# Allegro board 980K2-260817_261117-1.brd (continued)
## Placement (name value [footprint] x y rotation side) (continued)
NOREF#2378  -  []  247.95 286.12 90 top
NOREF#2379  -  []  168.42 208.62 0 top
NOREF#2380  -  []  164.64 241.15 90 top
NOREF#2381  -  []  216.26 203.76 90 top
NOREF#2382  -  []  286.32 202.32 0 top
NOREF#2383  -  []  275.58 262.67 90 top
NOREF#2384  -  []  209.55 237.49 0 top
NOREF#2385  -  []  241.75 206.13 0 top
NOREF#2386  -  []  158.64 173.37 90 top
NOREF#2387  -  []  163.97 208.95 0 top
NOREF#2388  -  []  141.83 265.99 0 top
NOREF#2389  -  []  195.05 283.39 0 top
NOREF#2390  -  []  269.12 256.43 90 top
NOREF#2391  -  []  233.6 222.39 0 top
NOREF#2392  -  []  122.2 178.35 0 top
NOREF#2393  -  []  219.55 180.49 90 top
NOREF#2394  -  []  231.19 223.92 0 top
NOREF#2395  -  []  163.97 210.55 90 top
NOREF#2396  -  []  271.24 193.03 90 top
NOREF#2397  -  []  163.84 210.87 90 top
NOREF#2398  -  []  151.11 253.35 0 top
NOREF#2399  -  []  147.77 251.31 0 top
NOREF#2400  -  []  140.83 268.59 90 top
NOREF#2401  -  []  213.64 299.09 0 top
NOREF#2402  -  []  171.22 234.89 90 top
NOREF#2403  -  []  149.84 284.11 0 top
NOREF#2404  -  []  239.27 264.78 90 top
NOREF#2405  -  []  220.43 224.38 90 top
NOREF#2406  -  []  241.75 209.17 0 top
NOREF#2407  -  []  151.76 227.33 0 top
NOREF#2408  -  []  290.89 206.13 0 top
NOREF#2409  -  []  272.63 172.86 0 top
NOREF#2410  -  []  228.35 217.95 90 top
NOREF#2411  -  []  202.57 291.95 0 top
NOREF#2412  -  []  147.43 284.11 90 top
NOREF#2413  -  []  288.42 260.97 90 top
NOREF#2414  -  []  230.48 175.77 0 top
NOREF#2415  -  []  270.15 266.89 90 top
NOREF#2416  -  []  228.99 251.93 0 top
NOREF#2417  -  []  283.97 202.09 0 top
NOREF#2418  -  []  271.24 197.85 90 top
NOREF#2419  -  []  184.16 185.63 90 top
NOREF#2420  -  []  159.4 272 0 top
NOREF#2421  -  []  174.07 210.89 90 top
NOREF#2422  -  []  266.28 257.85 90 top
NOREF#2423  -  []  170.89 269.17 0 top
NOREF#2424  -  []  283.84 210.87 90 top
NOREF#2425  -  []  244.64 241.15 90 top
NOREF#2426  -  []  152.25 272.17 0 top
NOREF#2427  -  []  179.73 238.35 0 top
NOREF#2428  -  []  267.43 278.27 0 top
NOREF#2429  -  []  156.02 251.31 0 top
NOREF#2430  -  []  171.22 294.24 90 top
NOREF#2431  -  []  156.57 182.05 0 top
NOREF#2432  -  []  261.85 246.47 0 top
NOREF#2433  -  []  221.55 205.11 90 top
NOREF#2434  -  []  233.83 172.21 90 top
NOREF#2435  -  []  253.36 201.22 0 top
NOREF#2436  -  []  269.84 213.7 0 top
NOREF#2437  -  []  150.88 228.6 90 top
NOREF#2438  -  []  249.52 270.32 90 top
NOREF#2439  -  []  274.07 196.43 90 top
NOREF#2440  -  []  163.84 267.82 90 top
NOREF#2441  -  []  192.25 272.17 0 top
NOREF#2442  -  []  276.7 193.03 90 top
NOREF#2443  -  []  155.92 195.7 90 top
NOREF#2444  -  []  197.25 180.62 0 top
NOREF#2445  -  []  227.77 252.78 0 top
NOREF#2446  -  []  256.83 287.03 0 top
NOREF#2447  -  []  228.78 282.65 0 top
NOREF#2448  -  []  268.89 392.33 90 top
NOREF#2449  -  []  176.55 254.49 90 top
NOREF#2450  -  []  195.49 228.7 90 top
NOREF#2451  -  []  197.37 240.3 90 top
NOREF#2452  -  []  237.04 244.35 0 top
NOREF#2453  -  []  173.34 17.15 90 top
NOREF#2454  -  []  153.95 256.75 0 top
NOREF#2455  -  []  150.77 219.22 90 top
NOREF#2456  -  []  169.52 272.86 90 top
NOREF#2457  -  []  191.76 167.33 0 top
NOREF#2458  -  []  164.44 232.28 90 top
NOREF#2459  -  []  151.76 167.33 0 top
NOREF#2460  -  []  245.38 226.23 0 top
NOREF#2461  -  []  203.84 270.87 90 top
NOREF#2462  -  []  173.36 261.22 0 top
NOREF#2463  -  []  188.32 182.05 0 top
NOREF#2464  -  []  236.84 227.33 0 top
NOREF#2465  -  []  142.81 186.81 0 top
NOREF#2466  -  []  218.95 264.09 0 top
NOREF#2467  -  []  226.16 253.35 0 top
NOREF#2468  -  []  288.42 265.58 0 top
NOREF#2469  -  []  139.08 265.79 0 top
NOREF#2470  -  []  237.04 244.35 0 top
NOREF#2471  -  []  253.62 229.09 90 top
NOREF#2472  -  []  279.27 200.97 90 top
NOREF#2473  -  []  254.09 267.27 90 top
NOREF#2474  -  []  232.25 218.02 0 top
NOREF#2475  -  []  215.65 244.35 0 top
NOREF#2476  -  []  125.38 226.23 0 top
NOREF#2477  -  []  141.55 205.11 90 top
NOREF#2478  -  []  203.97 260.64 90 top
NOREF#2479  -  []  152.61 456.29 0 top
NOREF#2480  -  []  147.3 280.35 0 top
NOREF#2481  -  []  277.37 256.43 90 top
NOREF#2482  -  []  156.7 197.85 90 top
NOREF#2483  -  []  129.17 291.95 0 top
NOREF#2484  -  []  135.11 201.22 90 top
NOREF#2485  -  []  276.79 231.3 0 top
NOREF#2486  -  []  144.16 196.43 90 top
NOREF#2487  -  []  155.56 235.77 0 top
NOREF#2488  -  []  229.12 240.3 90 top
NOREF#2489  -  []  275.15 176.17 90 top
NOREF#2490  -  []  270.6 233.69 90 top
NOREF#2491  -  []  159.4 205.9 0 top
NOREF#2492  -  []  224.04 185.96 0 top
NOREF#2493  -  []  214.43 292.23 0 top
NOREF#2494  -  []  156.33 227.9 90 top
NOREF#2495  -  []  264.24 18.69 0 top
NOREF#2496  -  []  273.39 253.03 90 top
NOREF#2497  -  []  270.48 235.77 0 top
NOREF#2498  -  []  163.4 236.38 0 top
NOREF#2499  -  []  191.91 251.6 90 top
NOREF#2500  -  []  195.56 175.77 0 top
NOREF#2501  -  []  226.16 226.14 90 top
NOREF#2502  -  []  283.97 267.5 90 top
NOREF#2503  -  []  249.52 210.32 90 top
NOREF#2504  -  []  168.54 262.09 0 top
NOREF#2505  -  []  234.07 256.43 90 top
NOREF#2506  -  []  264.04 256.75 0 top
NOREF#2507  -  []  289.52 210.32 90 top
NOREF#2508  -  []  230.88 168.6 90 top
NOREF#2509  -  []  147.45 269.24 0 top
NOREF#2510  -  []  240.23 236.17 90 top
NOREF#2511  -  []  269.12 240.3 90 top
NOREF#2512  -  []  168.54 202.09 0 top
NOREF#2513  -  []  277.03 238.07 0 top
NOREF#2514  -  []  268.32 198.18 0 top
NOREF#2515  -  []  218.97 211.91 90 top
NOREF#2516  -  []  241.44 184.35 0 top
NOREF#2517  -  []  209.55 237.49 0 top
NOREF#2518  -  []  271.79 256.75 0 top
NOREF#2519  -  []  178.97 211.91 90 top
NOREF#2520  -  []  270.88 168.6 90 top
NOREF#2521  -  []  138.75 457.2 0 top
NOREF#2522  -  []  239.4 202.09 0 top
NOREF#2523  -  []  84.45 359.42 0 top
NOREF#2524  -  []  175.02 208.14 90 top
NOREF#2525  -  []  157.71 172.86 0 top
NOREF#2526  -  []  182.03 229.03 90 top
NOREF#2527  -  []  274.33 207.37 90 top
NOREF#2528  -  []  178.95 201.55 0 top
NOREF#2529  -  []  273.56 173.37 90 top
NOREF#2530  -  []  157.37 256.43 90 top
NOREF#2531  -  []  150.63 259.3 0 top
NOREF#2532  -  []  277.25 251.93 0 top
NOREF#2533  -  []  273.18 211.85 90 top
NOREF#2534  -  []  239.4 264.45 90 top
NOREF#2535  -  []  224.04 196.75 0 top
NOREF#2536  -  []  258.95 206.12 0 top
NOREF#2537  -  []  239.27 271.67 0 top
NOREF#2538  -  []  272.25 282.59 0 top
NOREF#2539  -  []  190.6 173.69 0 top
NOREF#2540  -  []  221.55 209.94 90 top
NOREF#2541  -  []  152.72 192.78 0 top
NOREF#2542  -  []  284.95 260.42 90 top
NOREF#2543  -  []  225.41 226.99 90 top
NOREF#2544  -  []  192.13 274.25 0 top
NOREF#2545  -  []  186.43 296.46 90 top
NOREF#2546  -  []  222.87 286.99 0 top
NOREF#2547  -  []  239.72 274.65 90 top
NOREF#2548  -  []  197.71 173.69 90 top
NOREF#2549  -  []  255.11 261.22 90 top
NOREF#2550  -  []  230.77 283.79 90 top
NOREF#2551  -  []  190.77 279.22 90 top
NOREF#2552  -  []  153.83 172.21 90 top
NOREF#2553  -  []  203.04 236.5 90 top
NOREF#2554  -  []  283.97 205.9 0 top
NOREF#2555  -  []  191.73 172.54 0 top
NOREF#2556  -  []  243.84 211.67 0 top
NOREF#2557  -  []  211.25 184.35 0 top
NOREF#2558  -  []  228.19 187.71 0 top
NOREF#2559  -  []  197.18 236.17 90 top
NOREF#2560  -  []  236.7 181.72 90 top
NOREF#2561  -  []  196.52 221.12 0 top
NOREF#2562  -  []  163.97 267.5 90 top
NOREF#2563  -  []  100.95 17.15 0 top
NOREF#2564  -  []  195.05 274.25 0 top
NOREF#2565  -  []  192.13 284.66 0 top
NOREF#2566  -  []  173.45 184.35 0 top
NOREF#2567  -  []  148.99 191.93 0 top
NOREF#2568  -  []  272.25 212.18 90 top
NOREF#2569  -  []  279.4 267.5 90 top
NOREF#2570  -  []  159.4 265.9 0 top
NOREF#2571  -  []  188.44 181.72 90 top
NOREF#2572  -  []  221.55 269.94 90 top
NOREF#2573  -  []  170.89 206.13 0 top
NOREF#2574  -  []  173.65 179.15 0 top
NOREF#2575  -  []  248.94 221.73 0 top
NOREF#2576  -  []  146.28 197.85 90 top
NOREF#2577  -  []  259.55 234.49 0 top
NOREF#2578  -  []  161.84 235.2 0 top
NOREF#2579  -  []  273.6 276.55 0 top
NOREF#2580  -  []  178.95 208.91 0 top
NOREF#2581  -  []  273.98 178.07 0 top
NOREF#2582  -  []  167.95 286.12 90 top
NOREF#2583  -  []  171.65 293.3 90 top
NOREF#2584  -  []  270.97 239.57 90 top
NOREF#2585  -  []  276.57 182.05 0 top
NOREF#2586  -  []  227.99 238.35 0 top
NOREF#2587  -  []  185.42 274.72 90 top
NOREF#2588  -  []  194.33 204.33 90 top
NOREF#2589  -  []  237.74 166.36 90 top
NOREF#2590  -  []  267.99 238.35 0 top
NOREF#2591  -  []  259.08 205.79 0 top
NOREF#2592  -  []  129.44 260.67 0 top
NOREF#2593  -  []  243.84 210.87 90 top
NOREF#2594  -  []  254.07 210.89 90 top
NOREF#2595  -  []  161.12 188.11 90 top
NOREF#2596  -  []  294.09 200.42 90 top
NOREF#2597  -  []  228.78 228.49 0 top
NOREF#2598  -  []  214.43 292.23 0 top
NOREF#2599  -  []  154.39 222.02 90 top
NOREF#2600  -  []  233.56 233.37 90 top
NOREF#2601  -  []  159.4 267.5 90 top
NOREF#2602  -  []  191.19 223.92 0 top
NOREF#2603  -  []  279.22 195.7 90 top
NOREF#2604  -  []  163.84 270.87 90 top
NOREF#2605  -  []  277.71 172.86 0 top
NOREF#2606  -  []  179.08 268.59 0 top
NOREF#2607  -  []  204.95 260.42 90 top
NOREF#2608  -  []  159.27 274.21 0 top
NOREF#2609  -  []  137.28 286.47 0 top
NOREF#2610  -  []  261.03 207.69 90 top
NOREF#2611  -  []  179.55 294.49 0 top
NOREF#2612  -  []  226.28 193.03 90 top
NOREF#2613  -  []  232.63 233.69 0 top
NOREF#2614  -  []  232.51 235.77 0 top
NOREF#2615  -  []  156.8 214.65 90 top
NOREF#2616  -  []  151.7 274.65 90 top
NOREF#2617  -  []  196.61 173.37 90 top
NOREF#2618  -  []  178.97 18.69 0 top
NOREF#2619  -  []  174.34 82.65 0 top
NOREF#2620  -  []  211.05 232.28 90 top
NOREF#2621  -  []  195.17 221.32 90 top
NOREF#2622  -  []  147.3 226.19 0 top
NOREF#2623  -  []  237.37 256.43 90 top
NOREF#2624  -  []  209.17 291.95 0 top
NOREF#2625  -  []  85.84 157.62 0 top
NOREF#2626  -  []  154.39 216.17 90 top
NOREF#2627  -  []  150.15 206.89 90 top
NOREF#2628  -  []  159.44 179.15 0 top
NOREF#2629  -  []  288.42 261.77 0 top
NOREF#2630  -  []  288.39 396.29 0 top
NOREF#2631  -  []  234.07 196.43 90 top
NOREF#2632  -  []  183.49 187.06 90 top
NOREF#2633  -  []  131.22 294.89 90 top
NOREF#2634  -  []  153.18 211.85 90 top
NOREF#2635  -  []  193.39 253.03 90 top
NOREF#2636  -  []  150.6 233.69 90 top
NOREF#2637  -  []  85.59 155.57 90 top
NOREF#2638  -  []  94.87 102.74 90 top
NOREF#2639  -  []  251.25 244.35 0 top
NOREF#2640  -  []  268.44 257.85 90 top
NOREF#2641  -  []  156.57 245.63 90 top
NOREF#2642  -  []  283.97 264.45 90 top
NOREF#2643  -  []  155.17 212.18 0 top
NOREF#2644  -  []  274.39 222.02 90 top
NOREF#2645  -  []  149.72 226.19 0 top
NOREF#2646  -  []  239.27 213.41 90 top
NOREF#2647  -  []  231.95 238.07 0 top
NOREF#2648  -  []  131.26 244.35 0 top
NOREF#2649  -  []  259.08 201.22 0 top
NOREF#2650  -  []  217.29 247.78 0 top
NOREF#2651  -  []  252.87 227.4 90 top
NOREF#2652  -  []  271.19 283.92 0 top
NOREF#2653  -  []  203.97 207.5 90 top
NOREF#2654  -  []  288.54 202.09 0 top
NOREF#2655  -  []  146.96 256.43 90 top
NOREF#2656  -  []  239.44 179.15 0 top
NOREF#2657  -  []  228.78 288.49 0 top
NOREF#2658  -  []  268.32 258.18 0 top
NOREF#2659  -  []  159.4 262.09 0 top
NOREF#2660  -  []  246.32 262.32 0 top
NOREF#2661  -  []  263.49 187.06 90 top
NOREF#2662  -  []  153.18 217.69 90 top
NOREF#2663  -  []  273.94 191.93 0 top
NOREF#2664  -  []  258.35 204.47 0 top
NOREF#2665  -  []  147.77 197.6 0 top
NOREF#2666  -  []  279.4 268.95 0 top
NOREF#2667  -  []  196.57 258.18 0 top
NOREF#2668  -  []  261.55 262.57 90 top
NOREF#2669  -  []  250.89 206.13 0 top
NOREF#2670  -  []  268.44 241.72 90 top
NOREF#2671  -  []  239.4 270.55 90 top
NOREF#2672  -  []  198.47 82.65 0 top
NOREF#2673  -  []  272.87 248.11 90 top
NOREF#2674  -  []  231.91 256.43 90 top
NOREF#2675  -  []  228.32 258.18 0 top
NOREF#2676  -  []  154.33 207.37 90 top
NOREF#2677  -  []  155.15 176.17 90 top
NOREF#2678  -  []  152.51 175.77 0 top
NOREF#2679  -  []  183.36 187.38 0 top
NOREF#2680  -  []  153.95 251.93 0 top
NOREF#2681  -  []  219.55 234.49 0 top
NOREF#2682  -  []  249.52 204.23 90 top
NOREF#2683  -  []  189.67 250.01 0 top
NOREF#2684  -  []  80.49 135.25 0 top
NOREF#2685  -  []  283.84 261.77 0 top
NOREF#2686  -  []  227.77 192.78 0 top
NOREF#2687  -  []  267.3 280.35 0 top
NOREF#2688  -  []  156.57 253.35 0 top
NOREF#2689  -  []  192.72 197.6 0 top
NOREF#2690  -  []  199.4 204.45 90 top
NOREF#2691  -  []  275.17 216.75 0 top
NOREF#2692  -  []  189.24 185.31 90 top
NOREF#2693  -  []  223.49 187.06 90 top
NOREF#2694  -  []  234.39 222.02 90 top
NOREF#2695  -  []  254.43 292.23 0 top
NOREF#2696  -  []  272.25 222.59 0 top
NOREF#2697  -  []  260.59 244.98 90 top
NOREF#2698  -  []  269.72 226.19 0 top
NOREF#2699  -  []  279.72 283.79 90 top
NOREF#2700  -  []  152.25 222.59 90 top
NOREF#2701  -  []  156.7 257.85 90 top
NOREF#2702  -  []  281.75 274.76 0 top
NOREF#2703  -  []  148.81 190.88 90 top
NOREF#2704  -  []  273.6 216.55 0 top
NOREF#2705  -  []  255.02 268.14 90 top
NOREF#2706  -  []  302.59 389.27 90 top
NOREF#2707  -  []  284.95 204.23 90 top
NOREF#2708  -  []  192.63 233.69 90 top
NOREF#2709  -  []  260.83 261.22 90 top
NOREF#2710  -  []  190.15 206.89 90 top
NOREF#2711  -  []  193.83 232.21 90 top
NOREF#2712  -  []  232.25 282.59 90 top
NOREF#2713  -  []  283.84 207.82 90 top
NOREF#2714  -  []  264.04 185.96 0 top
NOREF#2715  -  []  236.52 221.12 0 top
NOREF#2716  -  []  131.05 292.28 90 top
NOREF#2717  -  []  128.94 265.53 0 top
NOREF#2718  -  []  234.39 226.59 90 top
NOREF#2719  -  []  234.33 264.33 90 top
NOREF#2720  -  []  227.3 226.19 0 top
NOREF#2721  -  []  238.91 172.21 90 top
NOREF#2722  -  []  256.98 205.11 90 top
NOREF#2723  -  []  259.08 263.76 0 top
NOREF#2724  -  []  270.77 273.37 90 top
NOREF#2725  -  []  260.43 284.38 90 top
NOREF#2726  -  []  279.27 201.77 0 top
NOREF#2727  -  []  194.33 264.33 90 top
NOREF#2728  -  []  283.97 270.55 90 top
NOREF#2729  -  []  279.4 207.5 90 top
NOREF#2730  -  []  284.95 212.86 90 top
NOREF#2731  -  []  176.74 456.29 0 top
NOREF#2732  -  []  221.6 17.15 0 top
NOREF#2733  -  []  275.49 18.69 90 top
NOREF#2734  -  []  136.98 205.11 90 top
NOREF#2735  -  []  148.78 184.35 0 top
NOREF#2736  -  []  267.3 220.35 0 top
NOREF#2737  -  []  273.27 193.35 0 top
NOREF#2738  -  []  187.8 264.99 90 top
NOREF#2739  -  []  239.4 265.9 0 top
NOREF#2740  -  []  201.84 235.2 0 top
NOREF#2741  -  []  242.2 178.35 0 top
NOREF#2742  -  []  156.02 181.47 0 top
NOREF#2743  -  []  196.1 216.42 90 top
NOREF#2744  -  []  284.95 210.32 90 top
NOREF#2745  -  []  172.37 392.33 90 top
NOREF#2746  -  []  146.17 226.14 90 top
NOREF#2747  -  []  259.72 213.6 90 top
NOREF#2748  -  []  191.79 196.75 0 top
NOREF#2749  -  []  228.32 185.63 0 top
NOREF#2750  -  []  159.27 205.58 0 top
NOREF#2751  -  []  233.76 195.7 90 top
NOREF#2752  -  []  230.2 389.27 90 top
NOREF#2753  -  []  197.25 256.75 0 top
NOREF#2754  -  []  260.95 261.55 90 top
NOREF#2755  -  []  244.64 181.15 90 top
NOREF#2756  -  []  153.27 253.35 0 top
NOREF#2757  -  []  175.02 268.14 90 top
NOREF#2758  -  []  193.95 191.93 0 top
NOREF#2759  -  []  165.38 286.23 0 top
NOREF#2760  -  []  149.12 191.6 90 top
NOREF#2761  -  []  272.25 278.02 0 top
NOREF#2762  -  []  239.65 212.56 0 top
NOREF#2763  -  []  278.64 173.37 90 top
NOREF#2764  -  []  191.19 288.49 0 top
NOREF#2765  -  []  284.95 207.27 90 top
NOREF#2766  -  []  168.54 260.64 90 top
NOREF#2767  -  []  146.16 200.17 90 top
NOREF#2768  -  []  153.56 173.37 90 top
NOREF#2769  -  []  259.73 178.35 0 top
NOREF#2770  -  []  231.76 227.33 0 top
NOREF#2771  -  []  199.72 279.22 90 top
NOREF#2772  -  []  266.28 197.85 90 top
NOREF#2773  -  []  164.95 212.86 90 top
NOREF#2774  -  []  199.44 179.15 0 top
NOREF#2775  -  []  191.11 193.35 0 top
NOREF#2776  -  []  139.55 294.49 0 top
NOREF#2777  -  []  187.8 269.99 0 top
NOREF#2778  -  []  216.98 205.11 90 top
NOREF#2779  -  []  271.76 167.33 0 top
NOREF#2780  -  []  236.52 285.69 0 top
NOREF#2781  -  []  157.81 389.27 90 top
NOREF#2782  -  []  131.84 21.69 90 top
NOREF#2783  -  []  195.68 173.69 0 top
NOREF#2784  -  []  159.27 208.62 0 top
NOREF#2785  -  []  151.71 171.3 0 top
NOREF#2786  -  []  229.84 219.54 90 top
NOREF#2787  -  []  272.25 218.02 0 top
NOREF#2788  -  []  268.32 185.63 0 top
NOREF#2789  -  []  175.84 262.57 90 top
NOREF#2790  -  []  238.64 233.37 90 top
NOREF#2791  -  []  151.11 193.35 0 top
NOREF#2792  -  []  270.97 179.57 90 top
NOREF#2793  -  []  165.04 293.3 90 top
NOREF#2794  -  []  199.06 238.07 0 top
NOREF#2795  -  []  269.67 250.01 0 top
NOREF#2796  -  []  189.12 240.3 90 top
NOREF#2797  -  []  279.27 264.78 90 top
NOREF#2798  -  []  227.45 269.24 0 top
NOREF#2799  -  []  148.78 244.35 0 top
NOREF#2800  -  []  242.57 291.95 0 top
NOREF#2801  -  []  232.87 188.11 90 top
NOREF#2802  -  []  234.78 176.5 90 top
NOREF#2803  -  []  196.79 171.3 0 top
NOREF#2804  -  []  180.95 201.55 90 top
NOREF#2805  -  []  161.44 184.35 0 top
NOREF#2806  -  []  216.98 265.11 90 top
NOREF#2807  -  []  130.92 291.95 90 top
NOREF#2808  -  []  277.37 196.43 90 top
NOREF#2809  -  []  162.2 178.35 0 top
NOREF#2810  -  []  271.19 278.07 0 top
NOREF#2811  -  []  222.87 273.02 0 top
NOREF#2812  -  []  153.95 191.93 0 top
NOREF#2813  -  []  218.95 208.91 0 top
NOREF#2814  -  []  209.55 237.49 0 top
NOREF#2815  -  []  194.78 236.5 90 top
NOREF#2816  -  []  263.36 253.35 0 top
NOREF#2817  -  []  279.22 190.88 90 top
NOREF#2818  -  []  259.4 458.49 0 top
NOREF#2819  -  []  152.63 173.69 0 top
NOREF#2820  -  []  147.3 220.35 0 top
NOREF#2821  -  []  189.84 284.11 90 top
NOREF#2822  -  []  236.7 193.03 90 top
NOREF#2823  -  []  275.17 212.18 0 top
NOREF#2824  -  []  168.42 205.58 0 top
NOREF#2825  -  []  122.85 237.22 0 top
NOREF#2826  -  []  147.99 178.35 0 top
NOREF#2827  -  []  230.97 239.57 90 top
NOREF#2828  -  []  148.32 193.35 0 top
NOREF#2829  -  []  279.4 273.09 90 top
NOREF#2830  -  []  250.02 214.45 0 top
NOREF#2831  -  []  190.98 244.35 0 top
NOREF#2832  -  []  197.25 240.62 0 top
NOREF#2833  -  []  159.4 214.54 0 top
NOREF#2834  -  []  181.85 246.47 0 top
NOREF#2835  -  []  261.85 306.46 0 top
NOREF#2836  -  []  194.33 267.37 90 top
NOREF#2837  -  []  235.17 216.75 90 top
NOREF#2838  -  []  180.83 201.22 90 top
NOREF#2839  -  []  288.42 208.62 0 top
NOREF#2840  -  []  106.68 128.02 0 top
NOREF#2841  -  []  261.55 265.11 90 top
NOREF#2842  -  []  140.95 261.55 90 top
NOREF#2843  -  []  186.96 191.6 90 top
NOREF#2844  -  []  134.04 210.63 90 top
NOREF#2845  -  []  155.68 233.69 0 top
NOREF#2846  -  []  243.97 207.5 90 top
NOREF#2847  -  []  146.16 253.35 0 top
NOREF#2848  -  []  149.84 224.11 90 top
NOREF#2849  -  []  273.18 244.35 0 top
NOREF#2850  -  []  228.35 283.79 90 top
NOREF#2851  -  []  155.17 216.75 90 top
NOREF#2852  -  []  138.95 206.12 0 top
NOREF#2853  -  []  197.18 176.17 90 top
NOREF#2854  -  []  274.39 216.17 90 top
NOREF#2855  -  []  244.95 210.32 90 top
NOREF#2856  -  []  187.77 252.78 0 top
NOREF#2857  -  []  144.04 256.75 0 top
NOREF#2858  -  []  273.6 282.39 0 top
NOREF#2859  -  []  188.81 255.7 90 top
NOREF#2860  -  []  229.84 284.11 90 top
NOREF#2861  -  []  239.27 200.97 90 top
NOREF#2862  -  []  135.24 261.55 90 top
NOREF#2863  -  []  152.72 252.5 0 top
NOREF#2864  -  []  190.97 255.7 90 top
NOREF#2865  -  []  197.04 184.35 0 top
NOREF#2866  -  []  155.05 223.39 0 top
NOREF#2867  -  []  170.89 262.32 0 top
NOREF#2868  -  []  202.2 178.35 0 top
NOREF#2869  -  []  273.39 193.03 90 top
NOREF#2870  -  []  235.68 173.69 0 top
NOREF#2871  -  []  232.63 173.69 0 top
NOREF#2872  -  []  150.6 233.69 0 top
NOREF#2873  -  []  283.97 204.45 90 top
NOREF#2874  -  []  203.97 202.09 0 top
NOREF#2875  -  []  191.71 171.3 0 top
NOREF#2876  -  []  169.52 210.32 90 top
NOREF#2877  -  []  224.16 245.63 90 top
NOREF#2878  -  []  159.65 212.56 0 top
NOREF#2879  -  []  243.4 236.38 0 top
NOREF#2880  -  []  229.24 245.31 90 top
NOREF#2881  -  []  248.54 200.64 90 top
NOREF#2882  -  []  227.23 18.69 90 top
NOREF#2883  -  []  149.24 245.31 90 top
NOREF#2884  -  []  155.49 228.7 90 top
NOREF#2885  -  []  157.37 240.3 90 top
NOREF#2886  -  []  163.84 213.41 90 top
NOREF#2887  -  []  251.21 294.89 90 top
NOREF#2888  -  []  137.28 272.5 0 top
NOREF#2889  -  []  228.44 193.03 90 top
NOREF#2890  -  []  230.41 168.7 90 top
NOREF#2891  -  []  254.09 207.27 90 top
NOREF#2892  -  []  193.6 222.39 0 top
NOREF#2893  -  []  254.09 264.23 90 top
NOREF#2894  -  []  276.8 280.49 90 top
NOREF#2895  -  []  239.27 204.78 90 top
NOREF#2896  -  []  150.77 279.22 90 top
NOREF#2897  -  []  275.51 454.29 90 top
NOREF#2898  -  []  270.77 279.22 90 top
NOREF#2899  -  []  181.6 248.12 0 top
NOREF#2900  -  []  179.55 240.49 90 top
NOREF#2901  -  []  129.17 231.95 0 top
NOREF#2902  -  []  124.32 291.95 90 top
NOREF#2903  -  []  199.4 274.54 0 top
NOREF#2904  -  []  275.68 173.69 90 top
NOREF#2905  -  []  197.37 251.6 90 top
NOREF#2906  -  []  254.04 210.63 90 top
NOREF#2907  -  []  270.97 195.7 90 top
NOREF#2908  -  []  130.58 263.21 90 top
NOREF#2909  -  []  190.77 213.37 90 top
NOREF#2910  -  []  232.13 214.25 0 top
NOREF#2911  -  []  147.43 218.27 90 top
NOREF#2912  -  []  269.84 284.11 0 top
NOREF#2913  -  []  243.97 202.09 0 top
NOREF#2914  -  []  195.17 272.17 90 top
NOREF#2915  -  []  135.15 265.24 90 top
NOREF#2916  -  []  266.01 195.7 90 top
NOREF#2917  -  []  210.89 202.32 0 top
NOREF#2918  -  []  146.96 191.6 90 top
NOREF#2919  -  []  268.99 240.62 0 top
NOREF#2920  -  []  188.81 250.88 90 top
NOREF#2921  -  []  243.92 289.94 0 top
NOREF#2922  -  []  199.22 179.57 90 top
NOREF#2923  -  []  86.61 153.16 0 top
NOREF#2924  -  []  244.95 204.23 90 top
NOREF#2925  -  []  186.28 197.85 90 top
NOREF#2926  -  []  231.24 193.03 90 top
NOREF#2927  -  []  140.43 224.38 90 top
NOREF#2928  -  []  259.73 238.35 0 top
NOREF#2929  -  []  239.4 214.54 0 top
NOREF#2930  -  []  248.42 265.58 0 top
NOREF#2931  -  []  141.6 248.12 0 top
NOREF#2932  -  []  283.84 273.41 90 top
NOREF#2933  -  []  188.78 222.65 0 top
NOREF#2934  -  []  191.98 280.75 90 top
NOREF#2935  -  []  216.55 220.49 0 top
NOREF#2936  -  []  199.22 255.7 90 top
NOREF#2937  -  []  215.02 268.14 90 top
NOREF#2938  -  []  143.49 193.03 90 top
NOREF#2939  -  []  243.84 273.41 90 top
NOREF#2940  -  []  159.24 244.35 0 top
NOREF#2941  -  []  239.27 211.67 0 top
NOREF#2942  -  []  168.54 204.45 90 top
NOREF#2943  -  []  188.35 283.79 90 top
NOREF#2944  -  []  252.55 284.49 0 top
NOREF#2945  -  []  283.97 274.54 0 top
NOREF#2946  -  []  266.96 251.6 90 top
NOREF#2947  -  []  157.04 184.35 0 top
NOREF#2948  -  []  268.99 191.93 0 top
NOREF#2949  -  []  321.5 18.69 0 top
NOREF#2950  -  []  156.02 236.37 0 top
NOREF#2951  -  []  280.23 176.17 90 top
NOREF#2952  -  []  207.98 226.38 90 top
NOREF#2953  -  []  184.16 196.43 90 top
NOREF#2954  -  []  184.16 245.63 90 top
NOREF#2955  -  []  228.99 191.93 0 top
NOREF#2956  -  []  152.11 171.4 0 top
NOREF#2957  -  []  191.11 260.17 90 top
NOREF#2958  -  []  275.96 228.6 90 top
NOREF#2959  -  []  236.45 187.71 0 top
NOREF#2960  -  []  259.72 273.6 90 top
NOREF#2961  -  []  161.75 206.13 0 top
NOREF#2962  -  []  156.7 193.03 90 top
NOREF#2963  -  []  277.59 235.77 0 top
NOREF#2964  -  []  196.38 181.15 90 top
NOREF#2965  -  []  266.43 296.46 90 top
NOREF#2966  -  []  146.01 195.7 90 top
NOREF#2967  -  []  235.96 168.6 90 top
NOREF#2968  -  []  284.95 264.23 90 top
NOREF#2969  -  []  170.89 202.32 0 top
NOREF#2970  -  []  199.06 178.07 0 top
NOREF#2971  -  []  269.72 275.77 0 top
NOREF#2972  -  []  232.63 233.69 90 top
NOREF#2973  -  []  165.04 233.3 90 top
NOREF#2974  -  []  155.68 173.69 0 top
NOREF#2975  -  []  179.73 178.35 0 top
NOREF#2976  -  []  279.27 204.78 90 top
NOREF#2977  -  []  243.97 268.95 0 top
NOREF#2978  -  []  256.55 194.49 90 top
NOREF#2979  -  []  232.25 222.59 0 top
NOREF#2980  -  []  199.22 250.88 90 top
NOREF#2981  -  []  283.97 200.64 90 top
NOREF#2982  -  []  168.94 221.73 0 top
NOREF#2983  -  []  231.11 258.18 0 top
NOREF#2984  -  []  203.04 176.5 90 top
NOREF#2985  -  []  247.95 226.12 90 top
NOREF#2986  -  []  169.17 231.95 0 top
NOREF#2987  -  []  199.4 208.95 0 top
NOREF#2988  -  []  254.09 260.42 90 top
NOREF#2989  -  []  155.58 202.67 90 top
NOREF#2990  -  []  259.55 240.49 90 top
NOREF#2991  -  []  121.84 235.2 0 top
NOREF#2992  -  []  218.35 267.01 0 top
NOREF#2993  -  []  230.98 184.35 0 top
NOREF#2994  -  []  254.09 204.23 90 top
NOREF#2995  -  []  187.03 231.4 0 top
NOREF#2996  -  []  209.52 207.27 90 top
NOREF#2997  -  []  276.8 274.65 90 top
NOREF#2998  -  []  258.35 269.04 0 top
NOREF#2999  -  []  188.99 196.75 0 top
NOREF#3000  -  []  192.51 235.77 0 top
NOREF#3001  -  []  232.13 274.25 0 top
NOREF#3002  -  []  248.54 208.95 0 top
NOREF#3003  -  []  168.42 201.77 0 top
NOREF#3004  -  []  258.95 266.12 0 top
NOREF#3005  -  []  263.89 245.24 90 top
NOREF#3006  -  []  196.33 227.9 90 top
NOREF#3007  -  []  276.7 241.72 90 top
NOREF#3008  -  []  133.66 179.15 0 top
NOREF#3009  -  []  158.91 232.21 90 top
NOREF#3010  -  []  99.98 392.33 90 top
NOREF#3011  -  []  132.55 250.49 90 top
NOREF#3012  -  []  122.2 178.35 0 top
NOREF#3013  -  []  131.26 184.35 0 top
NOREF#3014  -  []  149.29 276.17 90 top
NOREF#3015  -  []  139.08 268.59 0 top
NOREF#3016  -  []  268.32 245.63 0 top
NOREF#3017  -  []  233.6 282.39 0 top
NOREF#3018  -  []  176.26 263.76 90 top
NOREF#3019  -  []  157.25 180.62 0 top
NOREF#3020  -  []  179.73 178.35 0 top
NOREF#3021  -  []  163.97 213.09 90 top
NOREF#3022  -  []  188.44 193.03 90 top
NOREF#3023  -  []  158.11 232.1 0 top
NOREF#3024  -  []  275.17 276.75 0 top
NOREF#3025  -  []  288.42 268.62 0 top
NOREF#3026  -  []  138.83 292.23 0 top
NOREF#3027  -  []  163.97 265.9 0 top
NOREF#3028  -  []  258.95 204.09 0 top
NOREF#3029  -  []  192.13 214.25 0 top
NOREF#3030  -  []  124.55 148.49 90 top
NOREF#3031  -  []  168.54 265.9 0 top
NOREF#3032  -  []  191.98 226.59 90 top
NOREF#3033  -  []  235.05 274.25 0 top
NOREF#3034  -  []  272.11 171.4 0 top
NOREF#3035  -  []  223.36 253.35 0 top
NOREF#3036  -  []  176.98 265.11 90 top
NOREF#3037  -  []  88.14 134.87 0 top
NOREF#3038  -  []  209.52 212.86 90 top
NOREF#3039  -  []  272.13 274.25 0 top
NOREF#3040  -  []  90.48 16.49 0 top
NOREF#3041  -  []  248.54 267.5 90 top
NOREF#3042  -  []  247.98 226.38 90 top
NOREF#3043  -  []  246.32 212.22 0 top
NOREF#3044  -  []  141.85 232.5 0 top
NOREF#3045  -  []  265.42 274.72 90 top
NOREF#3046  -  []  238.64 173.37 90 top
NOREF#3047  -  []  167.98 286.38 90 top
NOREF#3048  -  []  135.66 244.35 0 top
NOREF#3049  -  []  185.61 257.6 0 top
NOREF#3050  -  []  270.41 168.7 90 top
NOREF#3051  -  []  191.46 227 0 top
NOREF#3052  -  []  188.32 258.18 0 top
NOREF#3053  -  []  122.44 232.28 0 top
NOREF#3054  -  []  143.61 456.29 90 top
NOREF#3055  -  []  174.09 204.23 90 top
NOREF#3056  -  []  222.03 289.03 90 top
NOREF#3057  -  []  238.11 232.1 0 top
NOREF#3058  -  []  278.91 172.21 90 top
NOREF#3059  -  []  237.71 173.69 0 top
NOREF#3060  -  []  276.57 245.63 90 top
NOREF#3061  -  []  244.95 207.27 90 top
NOREF#3062  -  []  123.4 236.38 0 top
NOREF#3063  -  []  208.54 260.64 90 top
NOREF#3064  -  []  136.63 292.23 0 top
NOREF#3065  -  []  186.01 184.91 90 top
NOREF#3066  -  []  251.05 292.28 90 top
NOREF#3067  -  []  193.03 172.1 0 top
NOREF#3068  -  []  229.72 281.62 0 top
NOREF#3069  -  []  228.95 206.89 0 top
NOREF#3070  -  []  150.6 173.69 90 top
NOREF#3071  -  []  271.11 198.18 0 top
NOREF#3072  -  []  288.54 208.95 0 top
NOREF#3073  -  []  191.71 231.3 0 top
NOREF#3074  -  []  150.98 184.35 0 top
NOREF#3075  -  []  163.4 296.38 0 top
NOREF#3076  -  []  264.04 191.93 0 top
NOREF#3077  -  []  196.02 197.6 0 top
NOREF#3078  -  []  184.04 196.75 0 top
NOREF#3079  -  []  214.09 264.23 90 top
NOREF#3080  -  []  260.95 264.09 90 top
NOREF#3081  -  []  243.84 271.67 0 top
NOREF#3082  -  []  122.57 291.95 0 top
NOREF#3083  -  []  239.22 179.57 90 top
NOREF#3084  -  []  206.32 269.17 0 top
NOREF#3085  -  []  147.8 265.39 90 top
NOREF#3086  -  []  283.04 176.5 90 top
NOREF#3087  -  []  176.63 292.23 0 top
NOREF#3088  -  []  147.05 269.24 0 top
NOREF#3089  -  []  149.78 228.3 0 top
NOREF#3090  -  []  144.04 185.96 0 top
NOREF#3091  -  []  161.75 262.32 0 top
NOREF#3092  -  []  131.05 245.49 90 top
NOREF#3093  -  []  277.37 180.3 90 top
NOREF#3094  -  []  191.98 220.75 90 top
NOREF#3095  -  []  243.04 236.5 90 top
NOREF#3096  -  []  165.38 226.23 0 top
NOREF#3097  -  []  266.16 200.17 90 top
NOREF#3098  -  []  89.76 144.42 90 top
NOREF#3099  -  []  203.97 273.09 90 top
NOREF#3100  -  []  223.89 185.24 90 top
NOREF#3101  -  []  260.95 266.12 90 top
NOREF#3102  -  []  272.13 224.66 0 top
NOREF#3103  -  []  248.45 295.2 0 top
NOREF#3104  -  []  191.95 238.07 0 top
NOREF#3105  -  []  241.75 202.32 0 top
NOREF#3106  -  []  264.24 20.69 90 top
NOREF#3107  -  []  209.55 237.49 0 top
NOREF#3108  -  []  183.49 197.85 90 top
NOREF#3109  -  []  174.09 207.27 90 top
NOREF#3110  -  []  276.1 211.85 90 top
NOREF#3111  -  []  144.16 251.6 90 top
NOREF#3112  -  []  163.97 207.5 90 top
NOREF#3113  -  []  267.05 209.24 0 top
NOREF#3114  -  []  196.7 181.72 90 top
NOREF#3115  -  []  250.89 209.17 0 top
NOREF#3116  -  []  168.54 208.95 0 top
NOREF#3117  -  []  95.35 396.29 0 top
NOREF#3118  -  []  152.13 220.09 0 top
NOREF#3119  -  []  156.57 258.18 0 top
NOREF#3120  -  []  189.84 213.7 90 top
NOREF#3121  -  []  284.64 181.15 90 top
NOREF#3122  -  []  148.19 247.71 0 top
NOREF#3123  -  []  176.38 204.09 90 top
NOREF#3124  -  []  272.63 173.69 0 top
NOREF#3125  -  []  177.25 236.5 90 top
NOREF#3126  -  []  129.05 292.28 0 top
NOREF#3127  -  []  203.84 268.62 0 top
NOREF#3128  -  []  251.25 184.35 0 top
NOREF#3129  -  []  138.35 211.84 0 top
NOREF#3130  -  []  297.39 456.29 0 top
NOREF#3131  -  []  267.43 224.11 0 top
NOREF#3132  -  []  288.37 18.69 0 top
NOREF#3133  -  []  144.71 247.68 90 top
NOREF#3134  -  []  114.61 17.78 0 top
NOREF#3135  -  []  191.24 257.85 90 top
NOREF#3136  -  []  226.28 253.03 90 top
NOREF#3137  -  []  209.52 200.42 90 top
NOREF#3138  -  []  149.21 17.15 0 top
NOREF#3139  -  []  132.26 248.4 0 top
NOREF#3140  -  []  186.43 236.47 90 top
NOREF#3141  -  []  221.55 207.14 90 top
NOREF#3142  -  []  196.57 185.63 90 top
NOREF#3143  -  []  261.59 234.15 0 top
NOREF#3144  -  []  236.1 276.42 90 top
NOREF#3145  -  []  199.27 210.87 90 top
NOREF#3146  -  []  174.04 270.63 90 top
NOREF#3147  -  []  191.11 258.18 0 top
NOREF#3148  -  []  155.96 168.6 90 top
NOREF#3149  -  []  269.84 224.11 0 top
NOREF#3150  -  []  235.17 221.32 0 top
NOREF#3151  -  []  232.11 171.4 0 top
NOREF#3152  -  []  142.88 273.02 0 top
NOREF#3153  -  []  131.65 233.3 90 top
NOREF#3154  -  []  309.55 14.59 90 top
NOREF#3155  -  []  248.42 201.77 0 top
NOREF#3156  -  []  241.75 214.76 0 top
NOREF#3157  -  []  88.44 107.76 0 top
NOREF#3158  -  []  236.7 253.03 90 top
NOREF#3159  -  []  135.43 276.18 0 top
NOREF#3160  -  []  219.73 238.35 0 top
NOREF#3161  -  []  205.38 286.23 0 top
NOREF#3162  -  []  140.59 184.98 90 top
NOREF#3163  -  []  233.18 277.69 90 top
NOREF#3164  -  []  161.41 167.9 90 top
NOREF#3165  -  []  221.03 207.69 90 top
NOREF#3166  -  []  148.78 184.35 0 top
NOREF#3167  -  []  188.78 244.35 0 top
NOREF#3168  -  []  157.59 235.77 0 top
NOREF#3169  -  []  216 456.29 0 top
NOREF#3170  -  []  170.89 266.13 0 top
NOREF#3171  -  []  258.35 264.47 0 top
NOREF#3172  -  []  234.33 267.37 90 top
NOREF#3173  -  []  138.95 268.91 0 top
NOREF#3174  -  []  149.29 289.79 0 top
NOREF#3175  -  []  203.92 229.94 0 top
NOREF#3176  -  []  250.89 202.32 0 top
NOREF#3177  -  []  163.84 273.41 90 top
NOREF#3178  -  []  218.35 264.47 0 top
NOREF#3179  -  []  196.02 257.6 0 top
NOREF#3180  -  []  156.38 181.15 90 top
NOREF#3181  -  []  212.64 264.47 0 top
NOREF#3182  -  []  276.8 214.65 90 top
NOREF#3183  -  []  154.63 286.99 0 top
NOREF#3184  -  []  252.64 204.47 0 top
NOREF#3185  -  []  199.4 272 0 top
NOREF#3186  -  []  259.73 238.35 0 top
NOREF#3187  -  []  186.16 253.35 0 top
NOREF#3188  -  []  133.36 201.22 0 top
NOREF#3189  -  []  273.94 196.75 0 top
NOREF#3190  -  []  147.99 178.35 0 top
NOREF#3191  -  []  221.85 232.5 0 top
NOREF#3192  -  []  151.46 227 0 top
NOREF#3193  -  []  184.04 191.93 0 top
NOREF#3194  -  []  130.92 231.95 90 top
NOREF#3195  -  []  149.67 236.37 90 top
NOREF#3196  -  []  258.95 261.55 0 top
NOREF#3197  -  []  234.07 251.6 90 top
NOREF#3198  -  []  289.52 260.42 90 top
NOREF#3199  -  []  184.04 251.93 0 top
NOREF#3200  -  []  181.55 262.57 90 top
NOREF#3201  -  []  186.16 226.14 90 top
NOREF#3202  -  []  273.6 222.39 0 top
NOREF#3203  -  []  163.84 268.62 0 top
NOREF#3204  -  []  174.38 204.09 0 top
NOREF#3205  -  []  241.75 272.22 0 top
NOREF#3206  -  []  175.11 201.22 90 top
NOREF#3207  -  []  166.32 209.17 0 top
NOREF#3208  -  []  231.53 233.37 90 top
NOREF#3209  -  []  154.51 259.27 90 top
NOREF#3210  -  []  171.25 244.35 0 top
NOREF#3211  -  []  196.52 276.55 0 top
NOREF#3212  -  []  161.75 266.13 0 top
NOREF#3213  -  []  233.76 250.88 90 top
NOREF#3214  -  []  146.43 236.47 90 top
NOREF#3215  -  []  277.25 180.62 0 top
NOREF#3216  -  []  265.41 226.99 90 top
NOREF#3217  -  []  232.63 172.86 0 top
NOREF#3218  -  []  179.55 234.49 0 top
NOREF#3219  -  []  197.5 245.31 90 top
NOREF#3220  -  []  277.18 236.17 90 top
NOREF#3221  -  []  252.87 287.4 90 top
NOREF#3222  -  []  188.99 256.75 0 top
NOREF#3223  -  []  194.39 282.02 90 top
NOREF#3224  -  []  199.4 202.09 0 top
NOREF#3225  -  []  266.28 193.03 90 top
NOREF#3226  -  []  196.02 241.47 0 top
NOREF#3227  -  []  186.28 257.85 90 top
NOREF#3228  -  []  146.43 222.5 90 top
NOREF#3229  -  []  288.54 205.9 0 top
NOREF#3230  -  []  213.45 244.35 0 top
NOREF#3231  -  []  181.55 202.57 90 top
NOREF#3232  -  []  191.18 179.15 0 top
NOREF#3233  -  []  239.22 250.88 90 top
NOREF#3234  -  []  208.42 265.58 0 top
NOREF#3235  -  []  149.78 228.3 0 top
NOREF#3236  -  []  182.87 286.99 0 top
NOREF#3237  -  []  156.61 173.37 90 top
NOREF#3238  -  []  213.69 14.59 90 top
NOREF#3239  -  []  146.83 256.75 0 top
NOREF#3240  -  []  271.11 200.17 90 top
NOREF#3241  -  []  279.4 208.95 0 top
NOREF#3242  -  []  140.83 201.22 90 top
NOREF#3243  -  []  258.95 208.91 0 top
NOREF#3244  -  []  159.27 264.78 90 top
NOREF#3245  -  []  193.56 233.37 90 top
NOREF#3246  -  []  272.63 233.69 0 top
NOREF#3247  -  []  151.7 280.49 90 top
NOREF#3248  -  []  268.78 184.35 0 top
NOREF#3249  -  []  243.84 200.97 90 top
NOREF#3250  -  []  213.65 239.15 0 top
NOREF#3251  -  []  268.44 253.03 90 top
NOREF#3252  -  []  276.57 253.35 0 top
NOREF#3253  -  []  193.27 198.18 0 top
NOREF#3254  -  []  244.76 392.33 90 top
NOREF#3255  -  []  165.38 226.23 0 top
NOREF#3256  -  []  197.59 175.77 0 top
NOREF#3257  -  []  143.49 197.85 90 top
NOREF#3258  -  []  279.27 211.67 0 top
NOREF#3259  -  []  196.45 247.71 0 top
NOREF#3260  -  []  226.83 251.93 0 top
NOREF#3261  -  []  174.09 260.42 90 top
NOREF#3262  -  []  156.52 221.12 0 top
NOREF#3263  -  []  162.26 236.17 90 top
NOREF#3264  -  []  170.92 231.95 90 top
NOREF#3265  -  []  227.77 197.6 0 top
NOREF#3266  -  []  204.64 181.15 90 top
NOREF#3267  -  []  188.81 195.7 90 top
NOREF#3268  -  []  226.7 223.05 90 top
NOREF#3269  -  []  155.97 21.69 90 top
NOREF#3270  -  []  227.05 209.24 0 top
NOREF#3271  -  []  266.83 256.75 0 top
NOREF#3272  -  []  78.11 0 90 top
NOREF#3273  -  []  136.63 232.23 0 top
NOREF#3274  -  []  188.81 190.88 90 top
NOREF#3275  -  []  153.98 238.07 0 top
NOREF#3276  -  []  267.8 264.99 90 top
NOREF#3277  -  []  141.85 246.47 0 top
NOREF#3278  -  []  283.97 210.55 90 top
NOREF#3279  -  []  146.83 191.93 0 top
NOREF#3280  -  []  288.54 200.64 90 top
NOREF#3281  -  []  149.12 196.43 90 top
NOREF#3282  -  []  196.33 167.9 90 top
NOREF#3283  -  []  228.81 255.7 90 top
NOREF#3284  -  []  159.4 212 0 top
NOREF#3285  -  []  147.12 276.42 0 top
NOREF#3286  -  []  140.95 264.09 90 top
NOREF#3287  -  []  139.08 201.22 0 top
NOREF#3288  -  []  224.16 256.43 90 top
NOREF#3289  -  []  223.36 258.18 0 top
NOREF#3290  -  []  207.04 239.09 0 top
NOREF#3291  -  []  262.81 197.6 0 top
NOREF#3292  -  []  132.87 227.4 90 top
NOREF#3293  -  []  188.78 244.35 0 top
NOREF#3294  -  []  267.99 178.35 0 top
NOREF#3295  -  []  196.8 214.65 90 top
NOREF#3296  -  []  326.72 389.27 90 top
NOREF#3297  -  []  173.64 299.09 0 top
NOREF#3298  -  []  279.06 178.07 0 top
NOREF#3299  -  []  174.09 267.27 90 top
NOREF#3300  -  []  229.84 213.7 90 top
NOREF#3301  -  []  190.88 228.6 90 top
NOREF#3302  -  []  143.89 185.24 90 top
NOREF#3303  -  []  237.5 245.31 90 top
NOREF#3304  -  []  276.52 281.12 0 top
NOREF#3305  -  []  196.02 192.78 0 top
NOREF#3306  -  []  188.44 197.85 90 top
NOREF#3307  -  []  150.56 252.5 0 top
NOREF#3308  -  []  209.05 292.28 0 top
NOREF#3309  -  []  249.52 207.27 90 top
NOREF#3310  -  []  283.84 268.62 0 top
NOREF#3311  -  []  272.25 282.59 90 top
NOREF#3312  -  []  175.65 244.35 0 top
NOREF#3313  -  []  152.66 166.36 90 top
NOREF#3314  -  []  276.7 253.03 90 top
NOREF#3315  -  []  179.08 203.76 0 top
NOREF#3316  -  []  179.72 273.6 90 top
NOREF#3317  -  []  134.43 292.23 0 top
NOREF#3318  -  []  186.28 193.03 90 top
NOREF#3319  -  []  197.25 196.75 0 top
NOREF#3320  -  []  233.94 196.75 0 top
NOREF#3321  -  []  146.88 280.75 90 top
NOREF#3322  -  []  197.25 191.93 0 top
NOREF#3323  -  []  219.08 201.22 0 top
NOREF#3324  -  []  162.87 16.49 0 top
NOREF#3325  -  []  248.42 208.62 0 top
NOREF#3326  -  []  159.27 268.62 0 top
NOREF#3327  -  []  230.77 219.22 90 top
NOREF#3328  -  []  231.79 196.75 0 top
NOREF#3329  -  []  155.92 190.88 90 top
NOREF#3330  -  []  176.98 205.11 90 top
NOREF#3331  -  []  239.27 268.62 0 top
NOREF#3332  -  []  167.74 456.29 90 top
NOREF#3333  -  []  273.6 226.96 0 top
NOREF#3334  -  []  224.16 185.63 90 top
NOREF#3335  -  []  231.24 257.85 90 top
NOREF#3336  -  []  279.72 219.22 90 top
NOREF#3337  -  []  204.61 234.24 90 top
NOREF#3338  -  []  194.07 251.6 90 top
NOREF#3339  -  []  210.02 214.45 0 top
NOREF#3340  -  []  209.55 237.49 0 top
NOREF#3341  -  []  277.37 251.6 90 top
NOREF#3342  -  []  228.81 195.7 90 top
NOREF#3343  -  []  226.16 200.17 90 top
NOREF#3344  -  []  199.27 211.67 0 top
NOREF#3345  -  []  228.78 244.35 0 top
NOREF#3346  -  []  279.22 239.57 90 top
NOREF#3347  -  []  198.91 232.21 90 top
NOREF#3348  -  []  279.4 212 0 top
NOREF#3349  -  []  174.07 270.89 90 top
NOREF#3350  -  []  154.86 454.29 90 top
NOREF#3351  -  []  201.75 202.32 0 top
NOREF#3352  -  []  183.89 185.24 90 top
NOREF#3353  -  []  132.26 237.5 0 top
NOREF#3354  -  []  267.77 257.6 0 top
NOREF#3355  -  []  146.96 196.43 90 top
NOREF#3356  -  []  168.42 267.82 90 top
NOREF#3357  -  []  213.78 207.01 0 top
NOREF#3358  -  []  243.84 204.78 90 top
NOREF#3359  -  []  136.55 280.49 0 top
NOREF#3360  -  []  227.43 284.11 0 top
NOREF#3361  -  []  248.42 260.97 90 top
NOREF#3362  -  []  146.01 190.88 90 top
NOREF#3363  -  []  139.49 266.31 90 top
NOREF#3364  -  []  190.41 228.7 90 top
NOREF#3365  -  []  133.95 281.02 90 top
NOREF#3366  -  []  192.25 212.18 90 top
NOREF#3367  -  []  276.52 221.12 0 top
NOREF#3368  -  []  89.74 135.6 90 top
NOREF#3369  -  []  163.84 260.97 90 top
NOREF#3370  -  []  281.41 167.9 90 top
NOREF#3371  -  []  152.25 272.17 90 top
NOREF#3372  -  []  244.95 272.86 90 top
NOREF#3373  -  []  261.85 232.5 0 top
NOREF#3374  -  []  162.26 176.17 90 top
NOREF#3375  -  []  170.02 274.45 0 top
NOREF#3376  -  []  241.75 274.76 0 top
NOREF#3377  -  []  199.24 184.35 0 top
NOREF#3378  -  []  159.4 260.64 90 top
NOREF#3379  -  []  157.04 184.35 0 top
NOREF#3380  -  []  231.24 253.03 90 top
NOREF#3381  -  []  149.68 334.65 0 top
NOREF#3382  -  []  230.6 233.69 90 top
NOREF#3383  -  []  191.79 191.93 0 top
NOREF#3384  -  []  274.33 267.37 90 top
NOREF#3385  -  []  236.57 253.35 0 top
NOREF#3386  -  []  150.77 273.37 90 top
NOREF#3387  -  []  284.95 200.42 90 top
NOREF#3388  -  []  253.78 207.01 0 top
NOREF#3389  -  []  168.54 268.95 0 top
NOREF#3390  -  []  234.39 286.59 90 top
NOREF#3391  -  []  277.71 233.69 90 top
NOREF#3392  -  []  125.08 17.15 90 top
NOREF#3393  -  []  242.2 238.35 0 top
NOREF#3394  -  []  167.74 456.29 0 top
NOREF#3395  -  []  290.89 266.13 0 top
NOREF#3396  -  []  271.98 286.59 90 top
NOREF#3397  -  []  199.27 273.41 90 top
NOREF#3398  -  []  151.7 283.69 0 top
NOREF#3399  -  []  253.65 179.15 0 top
NOREF#3400  -  []  269.84 273.7 90 top
NOREF#3401  -  []  194.39 222.02 90 top
NOREF#3402  -  []  228.99 256.75 0 top
NOREF#3403  -  []  203.84 200.97 90 top
NOREF#3404  -  []  193.76 255.7 90 top
NOREF#3405  -  []  131.26 244.35 0 top
NOREF#3406  -  []  202.44 232.28 0 top
NOREF#3407  -  []  276.61 173.37 90 top
NOREF#3408  -  []  248.94 281.73 0 top
NOREF#3409  -  []  193.18 217.69 90 top
NOREF#3410  -  []  270.6 173.69 90 top
NOREF#3411  -  []  243.97 265.9 0 top
NOREF#3412  -  []  277.5 245.31 90 top
NOREF#3413  -  []  189.12 180.3 90 top
NOREF#3414  -  []  182.81 246.81 0 top
NOREF#3415  -  []  164.61 294.89 90 top
NOREF#3416  -  []  289.52 264.23 90 top
NOREF#3417  -  []  207.95 286.12 90 top
NOREF#3418  -  []  229.84 224.11 90 top
NOREF#3419  -  []  168.42 200.97 90 top
NOREF#3420  -  []  223.49 247.06 90 top
NOREF#3421  -  []  198.11 232.1 0 top
NOREF#3422  -  []  259.55 294.49 0 top
NOREF#3423  -  []  172.64 204.47 0 top
NOREF#3424  -  []  272.25 212.18 0 top
NOREF#3425  -  []  279.4 213.09 90 top
NOREF#3426  -  []  279.4 272 0 top
NOREF#3427  -  []  178.95 261.55 0 top
NOREF#3428  -  []  284.95 272.86 90 top
NOREF#3429  -  []  208.54 207.5 90 top
NOREF#3430  -  []  268.78 222.65 0 top
NOREF#3431  -  []  227.9 265.84 90 top
NOREF#3432  -  []  256.26 203.76 90 top
NOREF#3433  -  []  161.75 202.32 0 top
NOREF#3434  -  []  268.81 250.88 90 top
NOREF#3435  -  []  125.25 291.4 0 top
NOREF#3436  -  []  248.54 264.45 90 top
NOREF#3437  -  []  279.72 223.79 90 top
NOREF#3438  -  []  125.08 17.15 0 top
NOREF#3439  -  []  131.22 294.24 90 top
NOREF#3440  -  []  283.84 214.21 0 top
NOREF#3441  -  []  267.77 192.78 0 top
NOREF#3442  -  []  271.76 227.33 0 top
NOREF#3443  -  []  279.4 214.54 0 top
NOREF#3444  -  []  215.11 261.22 90 top
NOREF#3445  -  []  271.19 218.07 0 top
NOREF#3446  -  []  153.03 172.1 0 top
NOREF#3447  -  []  229.72 275.77 0 top
NOREF#3448  -  []  152.63 172.86 0 top
NOREF#3449  -  []  131.05 185.49 90 top
NOREF#3450  -  []  109.55 389.27 90 top
NOREF#3451  -  []  181.55 205.11 90 top
NOREF#3452  -  []  251.65 293.3 90 top
NOREF#3453  -  []  267.99 238.35 0 top
NOREF#3454  -  []  284.95 270.32 90 top
NOREF#3455  -  []  163.97 205.9 0 top
NOREF#3456  -  []  276.7 181.72 90 top
NOREF#3457  -  []  196.52 281.12 0 top
NOREF#3458  -  []  248.42 264.78 90 top
NOREF#3459  -  []  95.33 18.69 0 top
NOREF#3460  -  []  154.78 176.5 90 top
NOREF#3461  -  []  149.29 282.02 90 top
NOREF#3462  -  []  157.37 191.6 90 top
NOREF#3463  -  []  231.71 171.3 0 top
NOREF#3464  -  []  273.03 232.1 0 top
NOREF#3465  -  []  236.8 214.65 90 top
NOREF#3466  -  []  159.4 204.45 90 top
NOREF#3467  -  []  232.72 192.78 0 top
NOREF#3468  -  []  162.44 292.28 0 top
NOREF#3469  -  []  265.61 252.78 0 top
NOREF#3470  -  []  278.45 14.59 90 top
NOREF#3471  -  []  254.04 270.63 90 top
NOREF#3472  -  []  128.94 221.73 0 top
NOREF#3473  -  []  219.08 263.76 0 top
NOREF#3474  -  []  195.17 276.75 0 top
NOREF#3475  -  []  203.97 200.64 90 top
NOREF#3476  -  []  233.18 244.35 0 top
NOREF#3477  -  []  248.54 205.9 0 top
NOREF#3478  -  []  220.83 203.76 90 top
NOREF#3479  -  []  140.83 263.76 90 top
NOREF#3480  -  []  254.33 389.27 90 top
NOREF#3481  -  []  149.84 273.7 90 top
NOREF#3482  -  []  132.55 284.49 0 top
NOREF#3483  -  []  239.27 201.77 0 top
NOREF#3484  -  []  156.7 253.03 90 top
NOREF#3485  -  []  230.48 235.77 0 top
NOREF#3486  -  []  159.27 261.77 0 top
NOREF#3487  -  []  192.25 282.59 0 top
NOREF#3488  -  []  153.6 226.96 0 top
NOREF#3489  -  []  187.45 209.24 0 top
NOREF#3490  -  []  127.95 226.12 90 top
NOREF#3491  -  []  187.3 280.35 0 top
NOREF#3492  -  []  213.36 261.22 0 top
NOREF#3493  -  []  189.84 224.11 90 top
NOREF#3494  -  []  231.73 232.54 0 top
NOREF#3495  -  []  233.39 253.03 90 top
NOREF#3496  -  []  161.75 209.17 0 top
NOREF#3497  -  []  144.04 196.75 0 top
NOREF#3498  -  []  157.71 233.69 0 top
NOREF#3499  -  []  204.95 267.27 90 top
NOREF#3500  -  []  235.27 458.49 0 top
NOREF#3501  -  []  275.56 235.77 0 top
NOREF#3502  -  []  250.02 274.45 0 top
NOREF#3503  -  []  178.35 204.47 0 top
NOREF#3504  -  []  192.66 166.36 90 top
NOREF#3505  -  []  199.27 205.58 0 top
NOREF#3506  -  []  140.83 261.22 90 top
NOREF#3507  -  []  226.16 260.17 90 top
NOREF#3508  -  []  246.73 82.65 0 top
NOREF#3509  -  []  166.32 266.13 0 top
NOREF#3510  -  []  253.78 267.01 0 top
NOREF#3511  -  []  195.15 236.17 90 top
NOREF#3512  -  []  219.08 208.59 0 top
NOREF#3513  -  []  220.95 206.12 90 top
NOREF#3514  -  []  164.95 272.86 90 top
NOREF#3515  -  []  161.75 212.22 0 top
NOREF#3516  -  []  186.7 237.02 90 top
NOREF#3517  -  []  208.45 235.2 0 top
NOREF#3518  -  []  154.33 204.33 90 top
NOREF#3519  -  []  256.55 220.49 0 top
NOREF#3520  -  []  88.14 155.19 0 top
NOREF#3521  -  []  156.8 220.49 90 top
NOREF#3522  -  []  209.05 232.28 0 top
NOREF#3523  -  []  197.71 233.69 0 top
NOREF#3524  -  []  209.55 237.49 0 top
NOREF#3525  -  []  196.84 227.33 0 top
NOREF#3526  -  []  158.89 259.3 0 top
NOREF#3527  -  []  227.43 278.27 0 top
NOREF#3528  -  []  147.8 205.39 90 top
NOREF#3529  -  []  135.15 263.21 90 top
NOREF#3530  -  []  273.39 257.85 90 top
NOREF#3531  -  []  199.22 195.7 90 top
NOREF#3532  -  []  233.03 232.1 0 top
NOREF#3533  -  []  156.61 233.37 90 top
NOREF#3534  -  []  212.55 224.49 0 top
NOREF#3535  -  []  212.64 204.47 0 top
NOREF#3536  -  []  153.39 197.85 90 top
NOREF#3537  -  []  235.17 212.18 90 top
NOREF#3538  -  []  186.16 212.17 90 top
NOREF#3539  -  []  226.16 212.17 90 top
NOREF#3540  -  []  88.14 151.13 90 top
NOREF#3541  -  []  192.25 278.02 0 top
NOREF#3542  -  []  207.95 226.12 90 top
NOREF#3543  -  []  151.91 196.43 90 top
NOREF#3544  -  []  232.25 222.59 90 top
NOREF#3545  -  []  196.1 276.42 90 top
NOREF#3546  -  []  216.55 194.49 90 top
NOREF#3547  -  []  179.55 180.49 90 top
NOREF#3548  -  []  259.08 265.79 0 top
NOREF#3549  -  []  282.26 236.17 90 top
NOREF#3550  -  []  157.74 166.36 90 top
NOREF#3551  -  []  227.05 269.24 0 top
NOREF#3552  -  []  252.55 224.49 0 top
NOREF#3553  -  []  290.89 202.32 0 top
NOREF#3554  -  []  204.44 292.28 90 top
NOREF#3555  -  []  159.4 270.55 90 top
NOREF#3556  -  []  271.91 191.6 90 top
NOREF#3557  -  []  156.33 167.9 90 top
NOREF#3558  -  []  89.76 145.32 0 top
NOREF#3559  -  []  242.44 232.28 0 top
NOREF#3560  -  []  230.15 206.89 90 top
NOREF#3561  -  []  283.84 201.77 0 top
NOREF#3562  -  []  271.53 233.37 90 top
NOREF#3563  -  []  145.61 252.5 0 top
NOREF#3564  -  []  156.38 241.15 90 top
NOREF#3565  -  []  144.16 191.6 90 top
NOREF#3566  -  []  190.77 283.79 90 top
NOREF#3567  -  []  226.7 297.01 90 top
NOREF#3568  -  []  258.35 209.04 0 top
NOREF#3569  -  []  209.55 237.49 0 top
NOREF#3570  -  []  203.84 265.58 0 top
NOREF#3571  -  []  171.25 184.35 0 top
NOREF#3572  -  []  239.4 212 0 top
NOREF#3573  -  []  156.02 248.11 90 top
NOREF#3574  -  []  149.12 240.3 90 top
NOREF#3575  -  []  277.25 191.93 0 top
NOREF#3576  -  []  229.72 226.19 0 top
NOREF#3577  -  []  272.66 226.35 90 top
NOREF#3578  -  []  142.88 286.99 0 top
NOREF#3579  -  []  152.25 282.59 0 top
NOREF#3580  -  []  230.97 250.88 90 top
NOREF#3581  -  []  288.39 456.29 90 top
NOREF#3582  -  []  154.63 274.65 90 top
NOREF#3583  -  []  195.17 221.32 0 top
NOREF#3584  -  []  163.97 202.09 0 top
NOREF#3585  -  []  273.76 195.7 90 top
NOREF#3586  -  []  232.25 278.02 90 top
NOREF#3587  -  []  188.35 277.95 90 top
NOREF#3588  -  []  269.86 17.15 90 top
NOREF#3589  -  []  249.52 260.42 90 top
NOREF#3590  -  []  101.95 82.65 0 top
NOREF#3591  -  []  187.3 226.19 0 top
NOREF#3592  -  []  236.79 231.3 0 top
NOREF#3593  -  []  149.12 251.6 90 top
NOREF#3594  -  []  149.67 252.5 90 top
NOREF#3595  -  []  235.05 214.25 0 top
NOREF#3596  -  []  148.99 180.62 0 top
NOREF#3597  -  []  272.87 188.11 90 top
NOREF#3598  -  []  229.55 188.99 90 top
NOREF#3599  -  []  253.24 261.55 0 top
NOREF#3600  -  []  193.76 190.88 90 top
NOREF#3601  -  []  244.95 267.27 90 top
NOREF#3602  -  []  172.55 224.49 0 top
NOREF#3603  -  []  228.32 245.63 0 top
NOREF#3604  -  []  188.35 217.95 90 top
NOREF#3605  -  []  199.27 270.87 90 top
NOREF#3606  -  []  147.43 224.11 90 top
NOREF#3607  -  []  208.54 202.09 0 top
NOREF#3608  -  []  239.4 273.09 90 top
NOREF#3609  -  []  138.95 208.91 0 top
NOREF#3610  -  []  125.38 226.23 0 top
NOREF#3611  -  []  155.78 237.5 90 top
NOREF#3612  -  []  258.97 211.91 90 top
NOREF#3613  -  []  188.32 193.35 0 top
NOREF#3614  -  []  201.75 214.76 0 top
NOREF#3615  -  []  130.02 274.45 0 top
NOREF#3616  -  []  270.97 250.88 90 top
NOREF#3617  -  []  193.6 286.96 0 top
NOREF#3618  -  []  133.4 281.8 90 top
NOREF#3619  -  []  203.97 267.5 90 top
NOREF#3620  -  []  187.77 181.47 0 top
NOREF#3621  -  []  203.84 273.41 90 top
NOREF#3622  -  []  218.35 269.04 0 top
NOREF#3623  -  []  189.55 188.99 90 top
NOREF#3624  -  []  230.56 252.78 0 top
NOREF#3625  -  []  239.4 268.95 0 top
NOREF#3626  -  []  220.59 244.98 90 top
NOREF#3627  -  []  172.87 227.4 90 top
NOREF#3628  -  []  199.27 264.78 90 top
NOREF#3629  -  []  196.45 187.71 0 top
NOREF#3630  -  []  264.04 251.93 0 top
NOREF#3631  -  []  215.84 202.57 90 top
NOREF#3632  -  []  235.17 272.17 0 top
NOREF#3633  -  []  268.44 181.72 90 top
NOREF#3634  -  []  267.43 218.27 0 top
NOREF#3635  -  []  233.39 197.85 90 top
NOREF#3636  -  []  218.95 204.09 0 top
NOREF#3637  -  []  254.43 232.23 0 top
NOREF#3638  -  []  141.55 207.14 90 top
NOREF#3639  -  []  167.95 226.12 90 top
NOREF#3640  -  []  152.13 214.25 0 top
NOREF#3641  -  []  269.84 213.7 90 top
NOREF#3642  -  []  279.4 200.64 90 top
NOREF#3643  -  []  196.57 245.63 90 top
NOREF#3644  -  []  181.85 306.46 0 top
NOREF#3645  -  []  268.78 228.49 0 top
NOREF#3646  -  []  156.57 245.63 0 top
NOREF#3647  -  []  169.17 291.95 0 top
NOREF#3648  -  []  195.17 216.75 0 top
